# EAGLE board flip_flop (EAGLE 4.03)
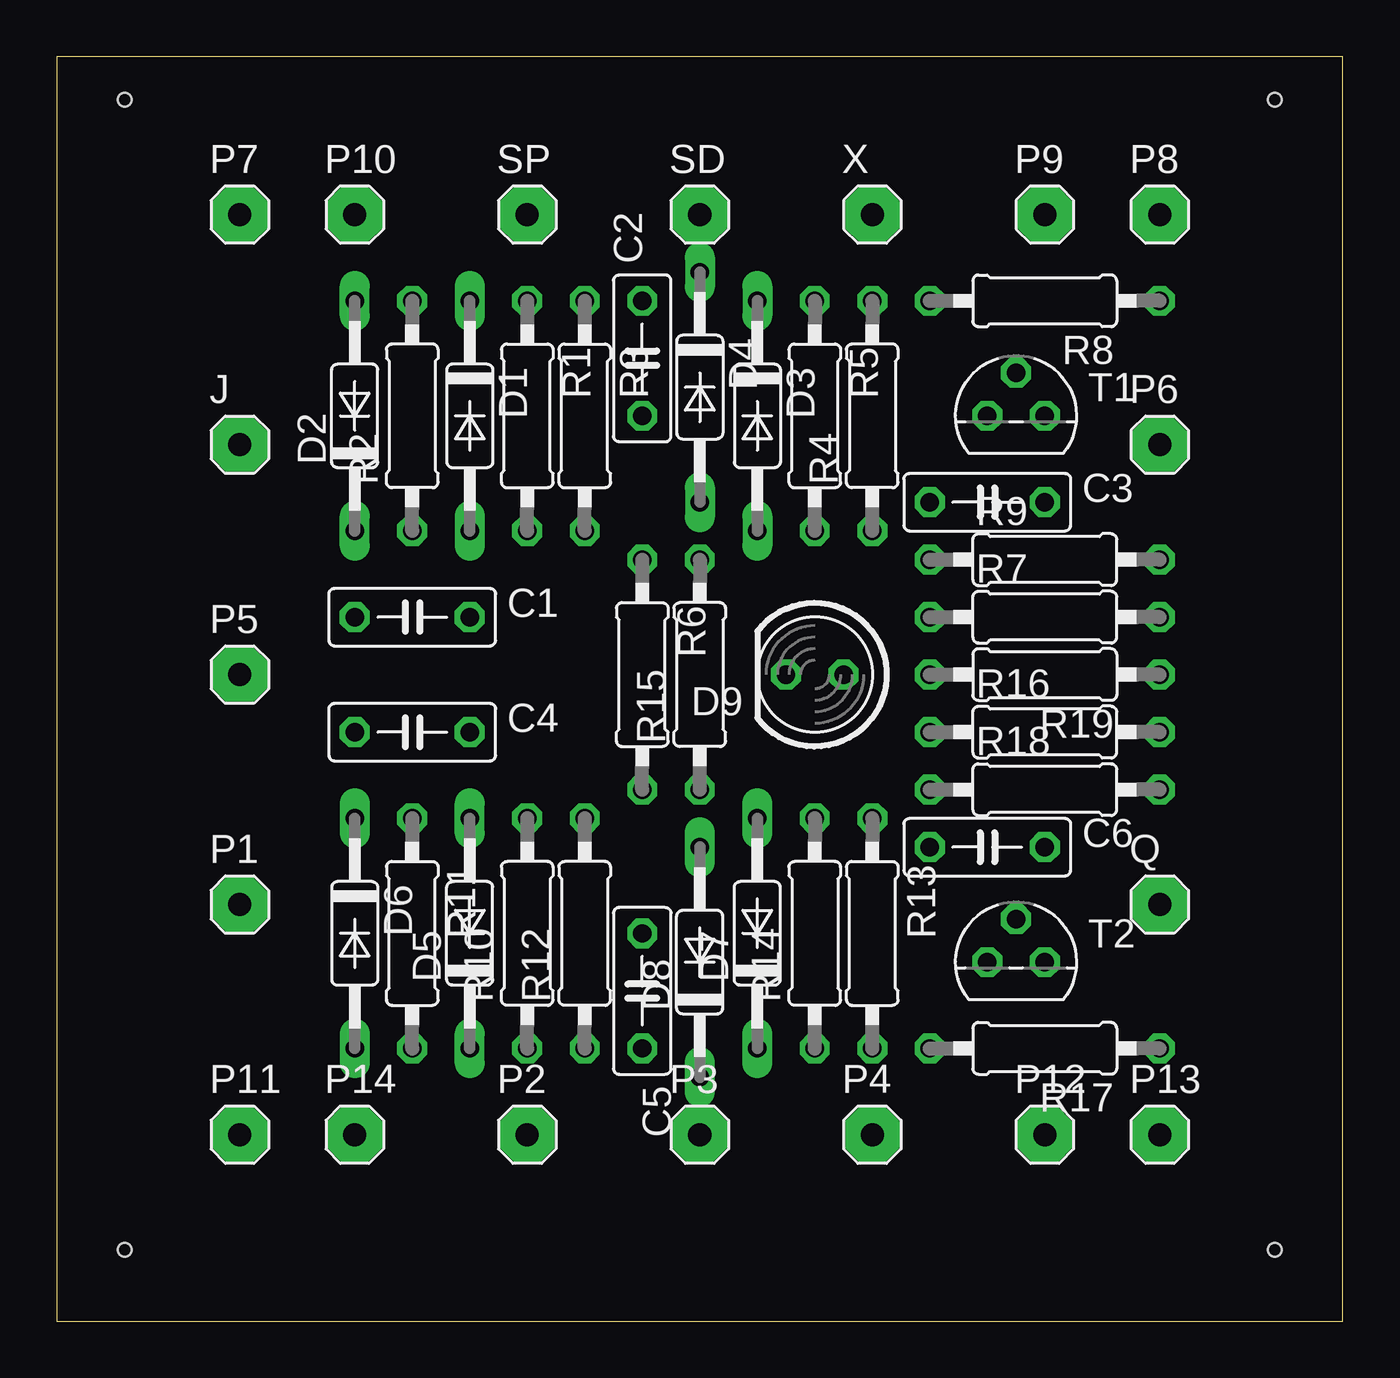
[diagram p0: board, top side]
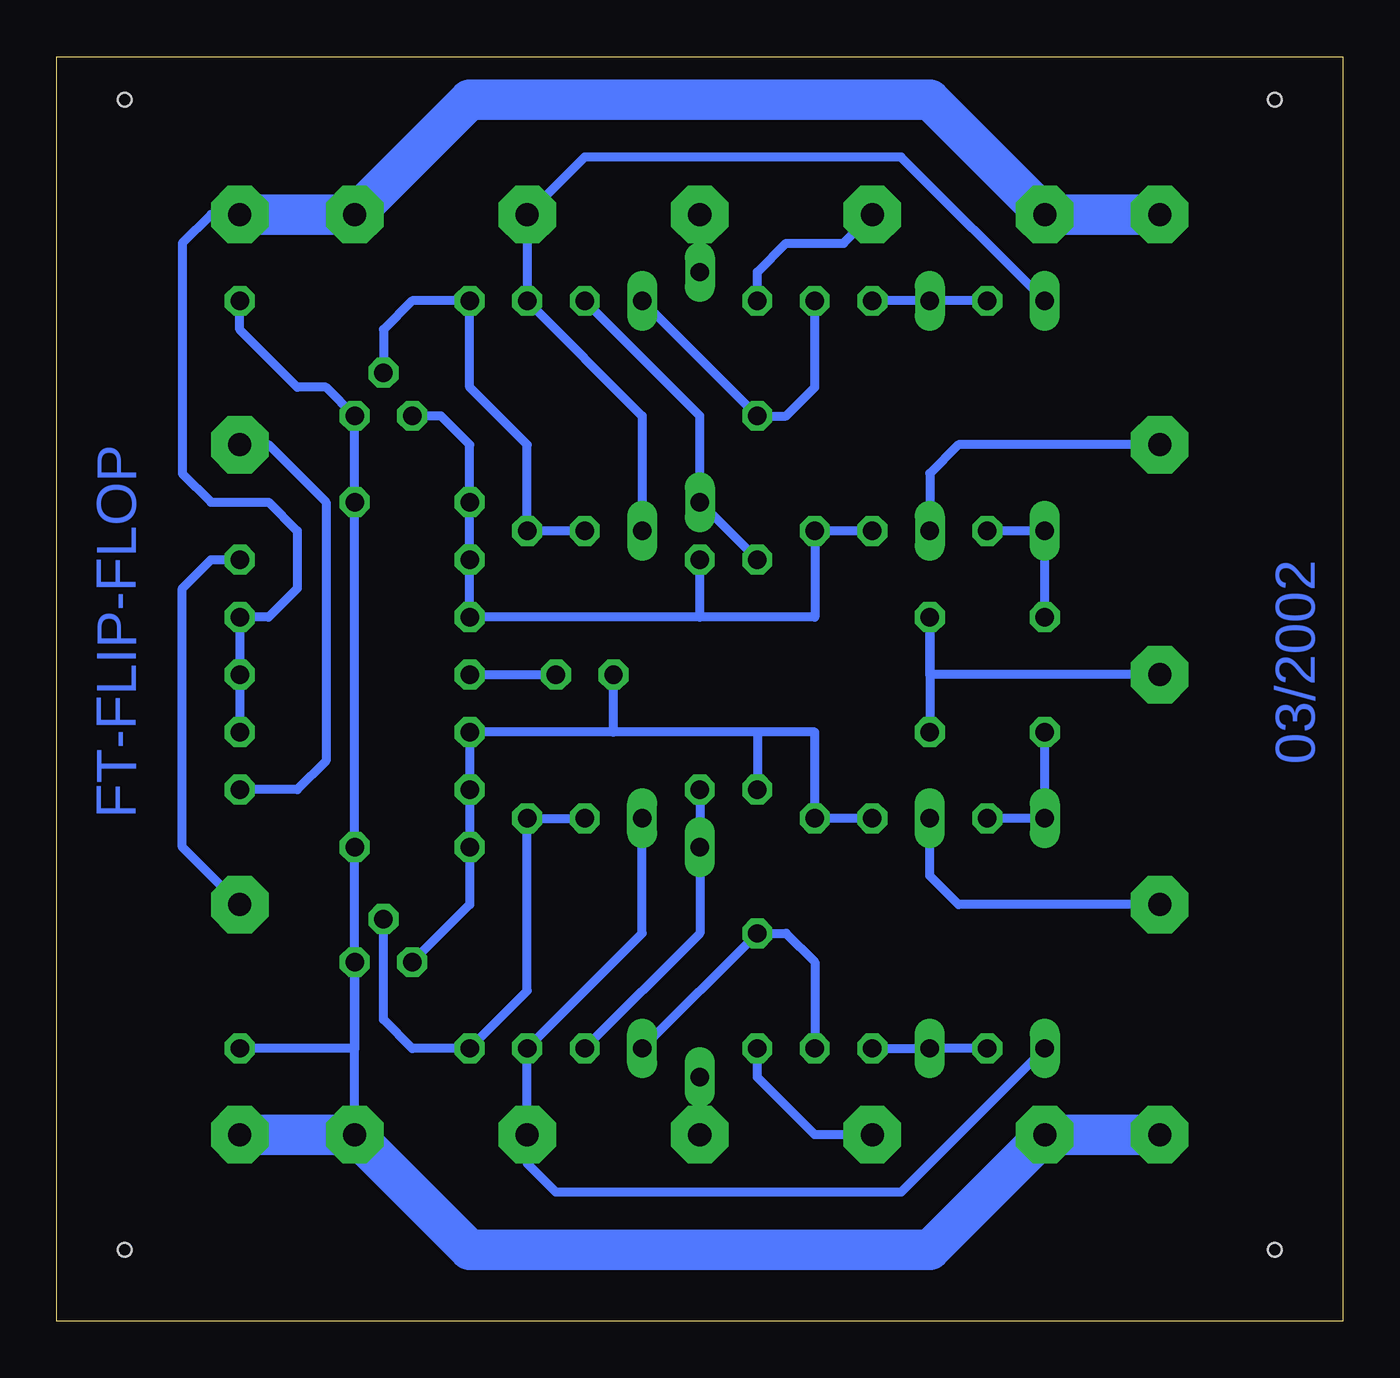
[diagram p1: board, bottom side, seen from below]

Size 56.82 x 55.87 mm. Coordinates in mm from the lower left corner, seen from the top.
Outline: 0,0 56.82,0 56.82,55.87 0,55.87 0,0
Copper layers used: Bottom
Holes 0.61 mm at 53.81,53.97 53.81,3.17 3.01,3.17 3.01,53.97

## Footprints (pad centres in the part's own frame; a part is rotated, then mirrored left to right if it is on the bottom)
C050-025X075 = drill 0.813 octagon: 1 -2.54,0; 2 2.54,0
DO35-10 = drill 0.813 long: A 5.08,0; C -5.08,0
LED5MM = drill 0.813 octagon: A -1.27,0; K 1.27,0
1X01 = drill 1.016 pad 2.54 octagon: 1 0,0
0207/10 = drill 0.813 octagon: 1 -5.08,0; 2 5.08,0
TO92 = drill 0.813 octagon: 1 1.27,0; 2 0,1.905; 3 -1.27,0

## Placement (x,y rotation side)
C1  22n  [C050-025X075]  15.71,31.11 0 top
C2  22n  [C050-025X075]  25.87,42.54 90 top
C3  22n  [C050-025X075]  41.11,36.19 0 top
C4  22n  [C050-025X075]  15.71,26.03 0 top
C5  22n  [C050-025X075]  25.87,14.6 270 top
C6  22n  [C050-025X075]  41.11,20.95 0 top
D1  1N4148  [DO35-10]  18.25,40 270 top
D2  1N4148  [DO35-10]  13.17,40 90 top
D3  1N4148  [DO35-10]  30.95,40 270 top
D4  1N4148  [DO35-10]  28.41,41.27 270 top
D5  1N4148  [DO35-10]  18.25,17.14 90 top
D6  1N4148  [DO35-10]  13.17,17.14 270 top
D7  1N4148  [DO35-10]  30.95,17.14 90 top
D8  1N4148  [DO35-10]  28.41,15.87 90 top
D9  LED5MM  [LED5MM]  33.49,28.57 180 top
J  J  [1X01]  8.09,38.73 0 top
P1  K  [1X01]  8.09,18.41 0 top
P2  RP  [1X01]  20.79,8.25 0 top
P3  RD  [1X01]  28.41,8.25 0 top
P4  X  [1X01]  36.03,8.25 0 top
P5  CP  [1X01]  8.09,28.57 0 top
P6  -Q  [1X01]  48.73,38.73 0 top
P7  +9V  [1X01]  8.09,48.89 0 top
P8  +9V  [1X01]  48.73,48.89 0 top
P9  +9V  [1X01]  43.65,48.89 0 top
P10  +9V  [1X01]  13.17,48.89 0 top
P11  GND  [1X01]  8.09,8.25 0 top
P12  GND  [1X01]  43.65,8.25 0 top
P13  GND  [1X01]  48.73,8.25 0 top
P14  GND  [1X01]  13.17,8.25 0 top
Q  Q  [1X01]  48.73,18.41 0 top
R1  10K  [0207/10]  20.79,40 270 top
R2  5K6  [0207/10]  15.71,40 90 top
R3  10K  [0207/10]  23.33,40 270 top
R4  6K8  [0207/10]  36.03,40 90 top
R5  10K  [0207/10]  33.49,40 270 top
R6  5K6  [0207/10]  25.87,28.57 270 top
R7  560R  [0207/10]  43.65,31.11 0 top
R8  5K6  [0207/10]  43.65,45.08 180 top
R9  82R  [0207/10]  43.65,33.65 0 top
R10  10K  [0207/10]  20.79,17.14 90 top
R11  5K6  [0207/10]  15.71,17.14 270 top
R12  10K  [0207/10]  23.33,17.14 90 top
R13  6K8  [0207/10]  36.03,17.14 270 top
R14  10K  [0207/10]  33.49,17.14 90 top
R15  5K6  [0207/10]  28.41,28.57 90 top
R16  1K  [0207/10]  43.65,26.03 0 top
R17  5K6  [0207/10]  43.65,12.06 180 top
R18  82R  [0207/10]  43.65,23.49 0 top
R19  220R  [0207/10]  43.65,28.57 180 top
SD  SD  [1X01]  28.41,48.89 0 top
SP  SP  [1X01]  20.79,48.89 0 top
T1  BC238  [TO92]  42.38,40 0 top
T2  BC238  [TO92]  42.38,15.87 0 top
X  X  [1X01]  36.03,48.89 0 top

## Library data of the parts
C1-C6 R1-R19 = rcl
D1-D8 = diode
D9 = led
J P1-P14 Q SD SP X = pinhead
T1 T2 = transistor-npn

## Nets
+9V: P7.1 P8.1 P9.1 P10.1 R7.2 R16.2 R19.1
GND: C3.2 C6.2 P11.1 P12.1 P13.1 P14.1 R8.1 R17.1 T1.1 T2.1
N$1: D1.A J.1
N$2: D1.C R1.1 R2.2
N$3: C6.1 D9.K R6.2 R10.2 R12.2 R16.1 R18.1 T2.3
N$4: C1.1 D2.C R2.1
N$5: Q.1 R9.2
N$6: C2.2 SP.1
N$8: C2.1 D3.C R3.1
N$9: P6.1 R18.2
N$10: D2.A D3.A R4.2 X.1
N$12: R4.1 R5.2 R8.2 T1.2
N$13: D4.A R5.1 R6.1
N$14: C3.1 R1.2 R3.2 R7.1 R9.1 R15.2 T1.3
N$15: D4.C SD.1
N$16: D8.A R14.1 R15.1
N$18: D8.C P3.1
N$19: R13.1 R14.2 R17.2 T2.2
N$20: D6.A D7.A P4.1 R13.2
N$22: C5.1 D7.C R12.1
N$24: C5.2 P2.1
N$25: D5.C R10.1 R11.2
N$27: D5.A P1.1
N$28: C4.1 D6.C R11.1
N$29: C1.2 C4.2 P5.1
N$36: D9.A R19.2

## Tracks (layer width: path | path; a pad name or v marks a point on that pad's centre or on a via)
+9V
  Bottom 0.406: P8.1 50,48.89 51.27,47.62 51.27,37.46 50,36.19 47.46,36.19 46.19,34.92 46.19,32.38 47.46,31.11 R7.2 R19.1 R16.2
  Bottom 1.778: P7.1 P10.1 18.25,53.97 38.57,53.97 P9.1 P8.1
GND
  Bottom 0.406: R8.1 48.73,43.81 46.19,41.27 44.92,41.27 T1.1 C3.2 C6.2 T2.1 | T2.1 43.65,12.06 R17.1 | P12.1 T2.1
  Bottom 1.778: P11.1 P14.1 18.25,3.17 38.57,3.17 P12.1 P13.1
N$1
  Bottom 0.406: J.1 16.98,38.73 18.25,37.46 D1.A
N$2
  Bottom 0.406: R2.2 D1.C R1.1
N$3
  Bottom 0.406: T2.3 38.57,18.41 C6.1 R18.1 R16.1 32.22,26.03 | R10.2 R12.2 23.33,26.03 25.87,26.03 | 25.87,26.03 R6.2 | 25.87,26.03 32.22,26.03 | 32.22,26.03 D9.K
N$4
  Bottom 0.406: C1.1 D2.C R2.1
N$5
  Bottom 0.406: Q.1 51.27,20.95 51.27,32.38 50,33.65 R9.2
N$6
  Bottom 0.406: C2.2 25.87,46.35 24.6,47.62 22.06,47.62 SP.1
N$8
  Bottom 0.406: R3.1 23.33,41.27 24.6,40 C2.1 D3.C
N$9
  Bottom 0.406: P6.1 47.46,38.73 44.92,36.19 44.92,24.76 46.19,23.49 R18.2
N$10
  Bottom 0.406: D2.A 19.52,51.43 33.49,51.43 X.1 R4.2 30.95,40 D3.A
N$12
  Bottom 0.406: T1.2 42.38,43.81 41.11,45.08 R8.2 38.57,41.27 36.03,38.73 R4.1 R5.2
N$13
  Bottom 0.406: R6.1 D4.A 28.41,40 R5.1
N$14
  Bottom 0.406: R1.2 R3.2 23.33,31.11 28.41,31.11 | 28.41,31.11 R15.2 | 28.41,31.11 R7.1 R9.1 C3.1 38.57,38.73 39.84,40 T1.3
N$15
  Bottom 0.406: SD.1 D4.C
N$16
  Bottom 0.406: R14.1 28.41,17.14 D8.A R15.1
N$18
  Bottom 0.406: D8.C P3.1
N$19
  Bottom 0.406: T2.2 42.38,13.33 41.11,12.06 R17.2 36.03,14.6 R13.1 R14.2
N$20
  Bottom 0.406: D7.A 30.95,17.14 R13.2 P4.1 36.03,6.98 34.76,5.71 19.52,5.71 D6.A
N$22
  Bottom 0.406: R12.1 23.33,15.87 24.6,17.14 C5.1 D7.C
N$24
  Bottom 0.406: P2.1 23.33,8.25 25.87,10.79 C5.2
N$25
  Bottom 0.406: R11.2 D5.C R10.1
N$27
  Bottom 0.406: D5.A 18.25,19.68 16.98,18.41 P1.1
N$28
  Bottom 0.406: C4.1 D6.C R11.1
N$29
  Bottom 0.406: P5.1 18.25,28.57 C1.2 C4.2
N$36
  Bottom 0.406: R19.2 D9.A

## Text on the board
Bottom: FT-FLIP-FLOP | 03/2002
